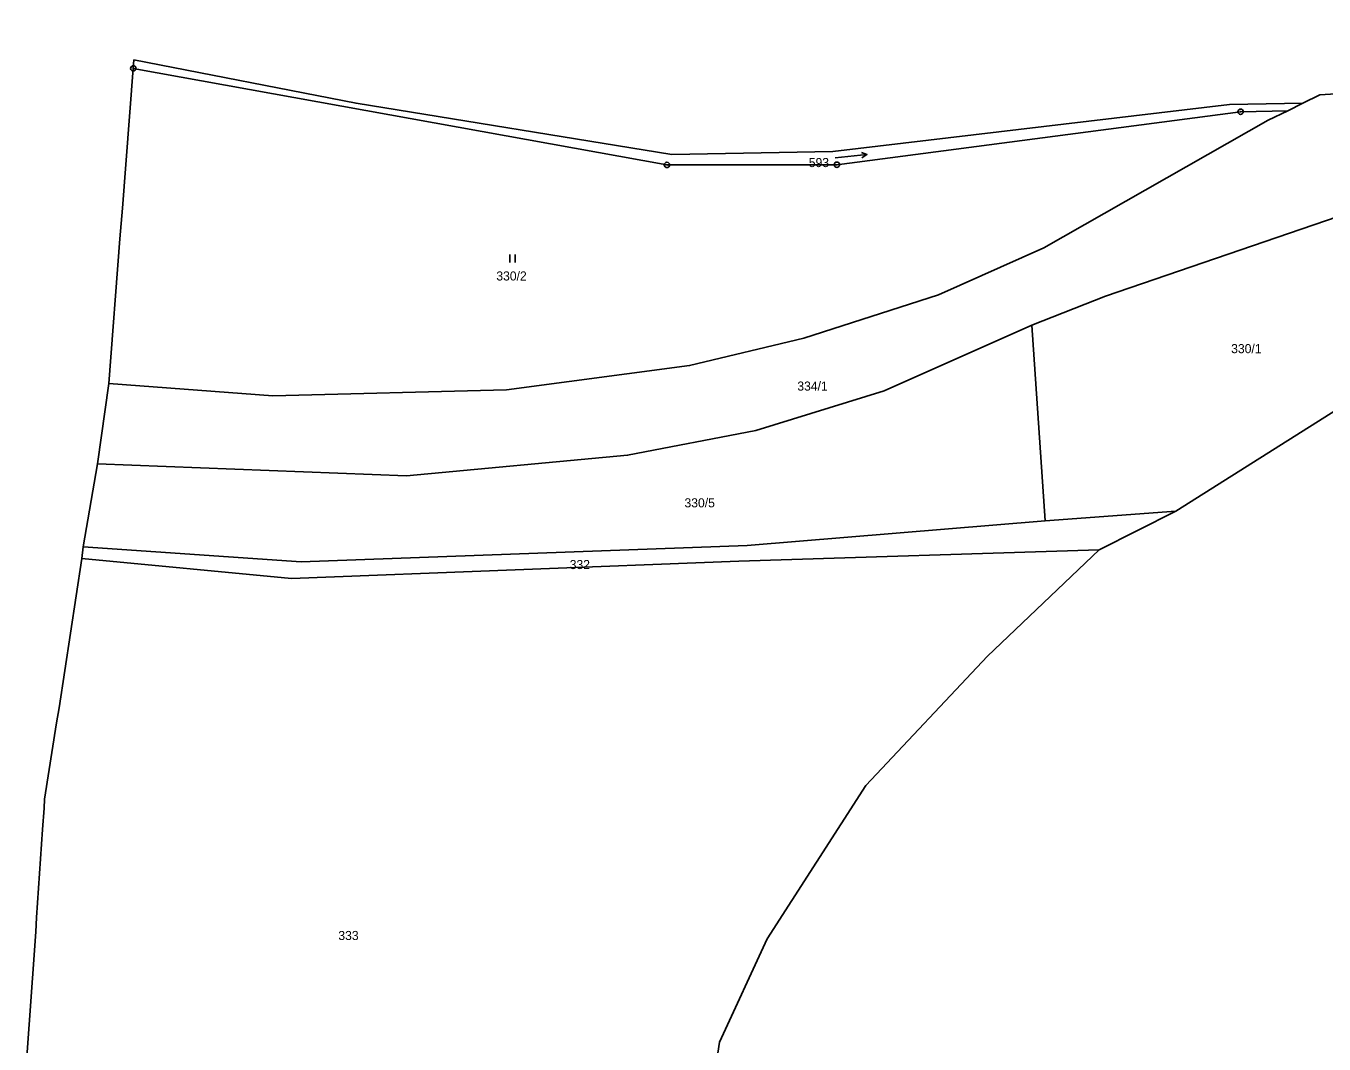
# Model space of a CAD drawing. Extents: x -754445 to -751443, y -1030748 to -1028224.
# Drawn here: x -754246.3 to -754003.3, y -1029236.8 to -1029046.3 of the extents above; entities that cross this region are included whole.
import ezdxf
from ezdxf.enums import TextEntityAlignment as Align

# ---------------------------------------------------------------- set-up
doc = ezdxf.new("R2010")
doc.units = 0
doc.header["$LTSCALE"] = 0.68
for name, color, linetype, lineweight in [('1', 7, 'Continuous', 25), ('3', 7, 'Continuous', 25), ('8', 7, 'Continuous', 25)]:
    doc.layers.add(name, color=color, linetype=linetype, lineweight=lineweight)
doc.layers.add('2', color=7, linetype='Continuous')

msp = doc.modelspace()

# ---------------------------------------------------------------- linework, layer by layer
at = {"layer": '1'}
for p, q in [((-754007.33, -1029060.78), (-754010.12, -1029062.18)), ((-754010.12, -1029062.18), (-754018.95, -1029062.36)), ((-754228.71, -1029086.16), (-754228.26, -1029080.4)), ((-754230.82, -1029113.19), (-754228.71, -1029086.16)), ((-754058.02, -1029102.28), (-754055.53, -1029138.95)), ((-754230.82, -1029113.19), (-754232.89, -1029128.23)), ((-754055.53, -1029138.95), (-754031.07, -1029137.12)), ((-754240.59, -1029176.72), (-754240.08, -1029173.9)), ((-754243.21, -1029196.72), (-754242.88, -1029192.72)), ((-754244.35, -1029213.19), (-754243.21, -1029196.72)), ((-754244.48, -1029215.83), (-754244.35, -1029213.19))]:
    msp.add_line(p, q, dxfattribs=at)
for points in [[(-754004.1, -1029059.17), (-753977.13, -1029057.51), (-753983.54, -1029046.3)], [(-754228.26, -1029080.4), (-754226.22, -1029054.24), (-754226.1, -1029052.64)], [(-754018.95, -1029062.36), (-754094.52, -1029072.28), (-754126.32, -1029072.31), (-754226.22, -1029054.24)], [(-754226.1, -1029052.64), (-754184.53, -1029060.76), (-754125.42, -1029070.38), (-754095.25, -1029069.77), (-754021, -1029061.03)], [(-754021, -1029061.03), (-754007.33, -1029060.78), (-754004.1, -1029059.17)], [(-754230.82, -1029113.19), (-754200.1, -1029115.5), (-754156.33, -1029114.4), (-754122.08, -1029109.86), (-754100.7, -1029104.76), (-754075.47, -1029096.62), (-754055.77, -1029087.82), (-754013.8, -1029063.9), (-754010.12, -1029062.18)], [(-753969.46, -1029070.58), (-753971.45, -1029071.49), (-754000.67, -1029081.94), (-754044.21, -1029096.88), (-754058.02, -1029102.28)], [(-753957.94, -1029093.91), (-753985.06, -1029108.08), (-754031.07, -1029137.12), (-754045.41, -1029144.32)], [(-754058.02, -1029102.28), (-754085.65, -1029114.59), (-754109.71, -1029122.01), (-754133.69, -1029126.65), (-754175.07, -1029130.48), (-754232.89, -1029128.23)], [(-754240.08, -1029173.9), (-754235.88, -1029146), (-754235.59, -1029143.79), (-754232.89, -1029128.23)], [(-754235.59, -1029143.79), (-754194.78, -1029146.61), (-754111.3, -1029143.56), (-754055.53, -1029138.95)], [(-754235.88, -1029146), (-754196.58, -1029149.7), (-754112.89, -1029146.47), (-754045.41, -1029144.32)], [(-754045.41, -1029144.32), (-754066.33, -1029164.25), (-754089.1, -1029188.44), (-754107.54, -1029217.16)], [(-754242.88, -1029192.72), (-754242.81, -1029191.01), (-754240.59, -1029176.72)], [(-754245.52, -1029261.36), (-754245.86, -1029259.67), (-754246.31, -1029241.84), (-754244.48, -1029215.83)], [(-754107.54, -1029217.16), (-754116.49, -1029236.48), (-754117.99, -1029246.39), (-754113.62, -1029265.22)]]:
    msp.add_lwpolyline(points, dxfattribs=at)
at = {"layer": '3'}
for p, q in [((-754088.898, -1029070.363), (-754089.818, -1029070.964)), ((-754155.711, -1029090.58), (-754155.711, -1029089.08)), ((-754154.71, -1029090.58), (-754154.71, -1029089.08))]:
    msp.add_line(p, q, dxfattribs=at)
msp.add_lwpolyline([(-754094.866, -1029070.99), (-754088.898, -1029070.363), (-754089.923, -1029069.967)], dxfattribs=at)
at = {"layer": '8'}
for centre, radius in [((-754226.22, -1029054.2399), 0.5), ((-754226.22, -1029054.2399), 0.0303), ((-754018.95, -1029062.3599), 0.5), ((-754018.95, -1029062.3599), 0.0303), ((-754126.32, -1029072.3099), 0.5), ((-754126.32, -1029072.3099), 0.0303), ((-754094.52, -1029072.2799), 0.5), ((-754094.52, -1029072.2799), 0.0303)]:
    msp.add_circle(centre, radius, dxfattribs=at)

# ---------------------------------------------------------------- texts
at = {"layer": '2'}
for s, p in [('593', (-754097.879, -1029072.71)), ('330/2', (-754155.42, -1029093.94)), ('330/1', (-754017.87, -1029107.54)), ('334/1', (-754099.08, -1029114.55)), ('330/5', (-754120.2, -1029136.4)), ('332', (-754142.629, -1029147.95)), ('333', (-754185.939, -1029217.38))]:
    msp.add_text(s, height=1.7, dxfattribs=at).set_placement(p, align=Align.CENTER)

doc.saveas('drawing.dxf')
